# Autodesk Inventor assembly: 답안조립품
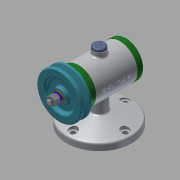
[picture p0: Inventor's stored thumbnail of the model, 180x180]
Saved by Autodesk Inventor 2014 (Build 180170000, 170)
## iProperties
Created: 2018-12
Part Number: 답안조립품
Document SubType Name: Assembly
Designer: kh
Author: kh
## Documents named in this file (15)
- C:\Users\kh\Desktop\481207V1013\답안조립품.iam
- C:\Users\kh\Desktop\481207V1013\본체.ipt
- C:\Users\kh\Desktop\481207V1013\V벨트풀리.ipt
- C:\Users\kh\Desktop\481207V1013\고무캡.ipt
- C:\Users\kh\Desktop\481207V1013\너트 M8.ipt
- 너트 M8.ipt
- C:\Users\kh\Desktop\481207V1013\뒤커버.ipt
- C:\Users\kh\Desktop\481207V1013\베어링 15 x 32 x 9.ipt
- C:\Users\kh\Desktop\481207V1013\볼트 M4 x 12.ipt
- C:\Users\kh\Desktop\481207V1013\스프링와셔 8.ipt
- C:\Users\kh\Desktop\481207V1013\앞커버.ipt
- C:\Users\kh\Desktop\481207V1013\오일 실 15 25 7.ipt
- C:\Users\kh\Desktop\481207V1013\와셔 8x17.ipt
- C:\Users\kh\Desktop\481207V1013\축.ipt
- C:\Users\kh\Desktop\481207V1013\키 3 x 3 x 12.ipt
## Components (2 placed, 2 different names)
1. V벨트풀리:1 — Mate:10, Mate:11, Mate:12, Mate:13, Mate:17
2. 고무캡:1 — Mate:14, Mate:15, Angle:4
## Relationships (8: Mate 7, Angle 1)
- Mate:10: V벨트풀리:1
- Mate:11: V벨트풀리:1
- Mate:12: V벨트풀리:1
- Mate:13: V벨트풀리:1
- Mate:14: 고무캡:1
- Mate:15: 고무캡:1
- Angle:4: 고무캡:1
- Mate:17: V벨트풀리:1
